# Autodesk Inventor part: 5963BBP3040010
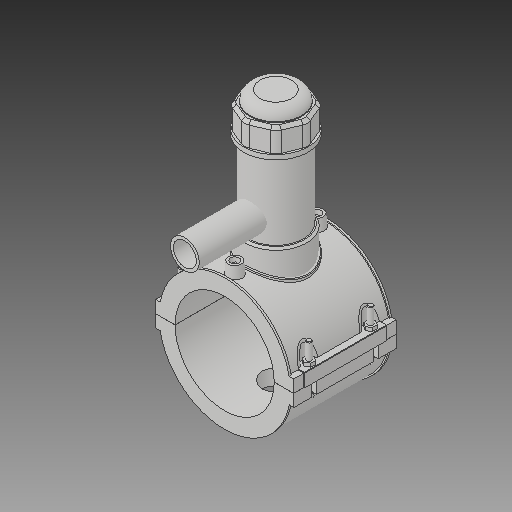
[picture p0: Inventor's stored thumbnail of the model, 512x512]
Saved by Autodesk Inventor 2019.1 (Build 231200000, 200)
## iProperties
Created: 2017-07
Part Number: 5963BBP3040010
Material: Generic
Description: PLASSON TAPPING SADDLE 4''IPS x 1''IPS
Document SubType Name: Modeling
Designer: KIM
Density: 1 g/cm^3
Appearance: Default
Author: KIM
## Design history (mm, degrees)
derived "5963BBP_5963BUP.ipt"
feature "Solid1::5963BBP_5963BUP.ipt"
feature "Solid2::5963BBP_5963BUP.ipt"
feature "Solid3::5963BBP_5963BUP.ipt"
tag "TaggingFeature1"
body "Solid1"
body "Solid2"
body "Solid3"
other parameters: "d0" = 114.1, "d2" = 159.004, "d3" = 28.525, "d4" = 118.11, "d5" = 0, "d6" = 0.1, "d8" = 0, "d19" = 6, "d20" = 6, "d21" = 70.866, "d23" = 0, "d24" = 35.433, "d26" = 0, "d27" = 3, "d28" = 3, "d29" = 3, "d30" = 38.03333, "d31" = 6, "d32" = 0, "d33" = 0, "d34" = 0.6, "d40" = 77.1316, "d41" = 74.165, "d43" = 0, "d45" = 0, "d47" = 145.031, "d70" = 15, "d72" = 0, "d73" = 6, "d75" = 5, "d76" = 0, "d77" = 5.705, "d78" = 87.05, "d79" = 15, "d80" = 47.244, "d82" = 5 deg, "d84" = 4, "d85" = 14, "d86" = 0, "d87" = 3, "d88" = 0, "d89" = 1, "d90" = 1, "d91" = 94.488, "d92" = 0, "d93" = 0.5, "d94" = 60.05263, "d96" = 151.2966, "d97" = 2.3622, "d98" = 0, "d102" = 1.141, "d120" = 140 deg, "d121" = 24.228, "d122" = 20 deg, "d123" = 296.66, "d124" = 88.998, "d126" = 0, "d143" = 117.523, "d145" = 26.33077, "d149" = 1.7115, "d150" = 28.96385, "d153" = 118.11, "d154" = 0, "d156" = 74.165, "d157" = 160 deg, "d159" = 6.846, "d161" = 1.7115, "d162" = 70.866, "d163" = 0, "d164" = 57.05, "d167" = 11.41, "d168" = 72.3561, "d170" = 3.2805, "d172" = 0, "d173" = 1, "d175" = 57.05, "d176" = 20 deg, "d177" = 7.987, "d178" = 34.23, "d180" = 0, "d183" = 13.692, "d184" = 6.3896, "d185" = 38.38575, "d186" = 38.38575, "d187" = 74.165, "d188" = 10.269, "d189" = 7.987, "d190" = 0, "d191" = 111.2475, "d193" = 6.9984, "d194" = 4.13385, "d195" = 90 deg, "d197" = 0, "d199" = 0, "d200" = 17.115, "d202" = 0, "d203" = 177.038, "d204" = 70.45675, "d205" = 51.9155, "d206" = 63.04025, "d207" = 132.7785, "d208" = 138.08964, "d209" = 164.64534, "d210" = 63.7819, "d211" = 74.165, "d212" = 59.332, "d213" = 43.5366, "d216" = 0, "d217" = 11.41, "d218" = 11.41, "d219" = 2.282, "d222" = 114.1, "d224" = 0, "d225" = 65.024, "d226" = 33.3, "d227" = 26.64, "d228" = 104.902, "d230" = 3.423, "d_" = 114.1, "B_" = 159.004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
